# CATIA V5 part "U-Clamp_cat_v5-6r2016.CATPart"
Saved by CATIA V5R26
Part number: U-Clamp
Bounding box of the stored display mesh (mm): x -23 to 23, y -6.5 to 6.5, z -25 to 29
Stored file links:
  D:\_Deepak\CATIA\CATIA V5 2015 Parts Files\Tutorial Files\Tutorials\c14_catia_v5_6r2016_tut\c14tut2\c14tut2.CATParts\U-Clamp_cat_v5-6r2016.CATPart
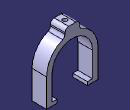
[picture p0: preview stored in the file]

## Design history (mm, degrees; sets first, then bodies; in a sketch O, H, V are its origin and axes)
Body1 (main body)
  Sketch1 on zx-plane, origin (0, 0, 0), H (-1, 0, 0), V (0, 0, 1)
    arc A1 centre (0, 0) radius 18 from (18, 0) to (-18, 0) ccw
    point P1 (-18, 0)
    point P2 (18, 0)
    line L1 (-18, 0) -> (-18, -22)
    point P3 (-18, -22)
    line L2 (-18, -22) -> (-13.5, -22)
    point P4 (-13.5, -22)
    line L3 (-13.5, -22) -> (-13.5, -25)
    point P5 (-13.5, -25)
    line L4 (-13.5, -25) -> (-23, -25)
    point P6 (-23, -25)
    line L5 (-23, -25) -> (-23, 0)
    point P7 (-23, 0)
    arc A2 centre (0, 0) radius 23 from (-23, 0) to (-6.5, 22.0624) cw
    point P9 (23, 0)
    point P10 (23, 0)
    point P11 (23, -25)
    line L6 (23, -25) -> (23, 0)
    point P12 (13.5, -25)
    line L7 (13.5, -25) -> (23, -25)
    point P13 (13.5, -22)
    line L8 (13.5, -22) -> (13.5, -25)
    point P14 (18, -22)
    line L9 (18, -22) -> (13.5, -22)
    point P15 (18, 0)
    line L10 (18, 0) -> (18, -22)
    line L11 (-6.5, 22.0624) -> (-6.5, 29)
    point P16 (-6.5, 29)
    line L12 (-6.5, 29) -> (6.5, 29)
    point P17 (6.5, 29)
    line L13 (6.5, 29) -> (6.5, 22.0624)
    point P18 (6.5, 22.0624)
    arc A3 centre (0, 0) radius 23 from (6.5, 22.0624) to (23, 0) cw
    distance L3 V = 13.5
    distance H L4 = 25
    distance V L5 = 23
    distance P16 P17 = 13
    distance L11 V = 6.5
    distance L7 L12 = 54
    distance L1 L5 = 5
    length L3 = 3
    coincidence: P1 H, P2 H, P7 H, A2 P18, A2 A3, P2 P15, P9 P10
    tangency: L1 A1, A2 L5
    horizontal: L2 H, L4 H, L12 H
    vertical: L3 V, L5 V, L11 V, L13 V
    concentricity: A2 A1
    symmetry: P7 P10 V, P6 P11 V, L5 L6 V, P5 P12 V, L4 L7 V, P4 P13 V, L3 L8 V, P3 P14 V, L2 L9 V, P1 P15 V, L1 L10 V
  Pad1: profile Sketch1, direction (0, -1, 0), length 6.5, mirrored extent
  Fillet1: radius 3.302, on 4 edges
  Sketch2 on face of Pad1, origin (-0.057, 2.6412, 29), H (1, 0, 0), V (0, 1, 0)
    point P1 (0.057, -2.6412)
    reference intersected line E1 through (0.057, 0) direction (0, 1) from yz-plane
    reference intersected line E2 through (0, -2.6412) direction (-1, 0) from zx-plane
    coincidence: E1 P1, E2 P1
  Hole1: placed by Sketch2, at (0, 0, 29) direction (0, 0, -1), diameter 4, depth 25.4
